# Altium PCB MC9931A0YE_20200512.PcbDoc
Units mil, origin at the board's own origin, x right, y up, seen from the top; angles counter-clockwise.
Board outline 1358.13 x 1061.66 mil, 2 copper layers (Top Layer, Bottom Layer); 25 components, 18 nets, 85 pads, 79 vias.
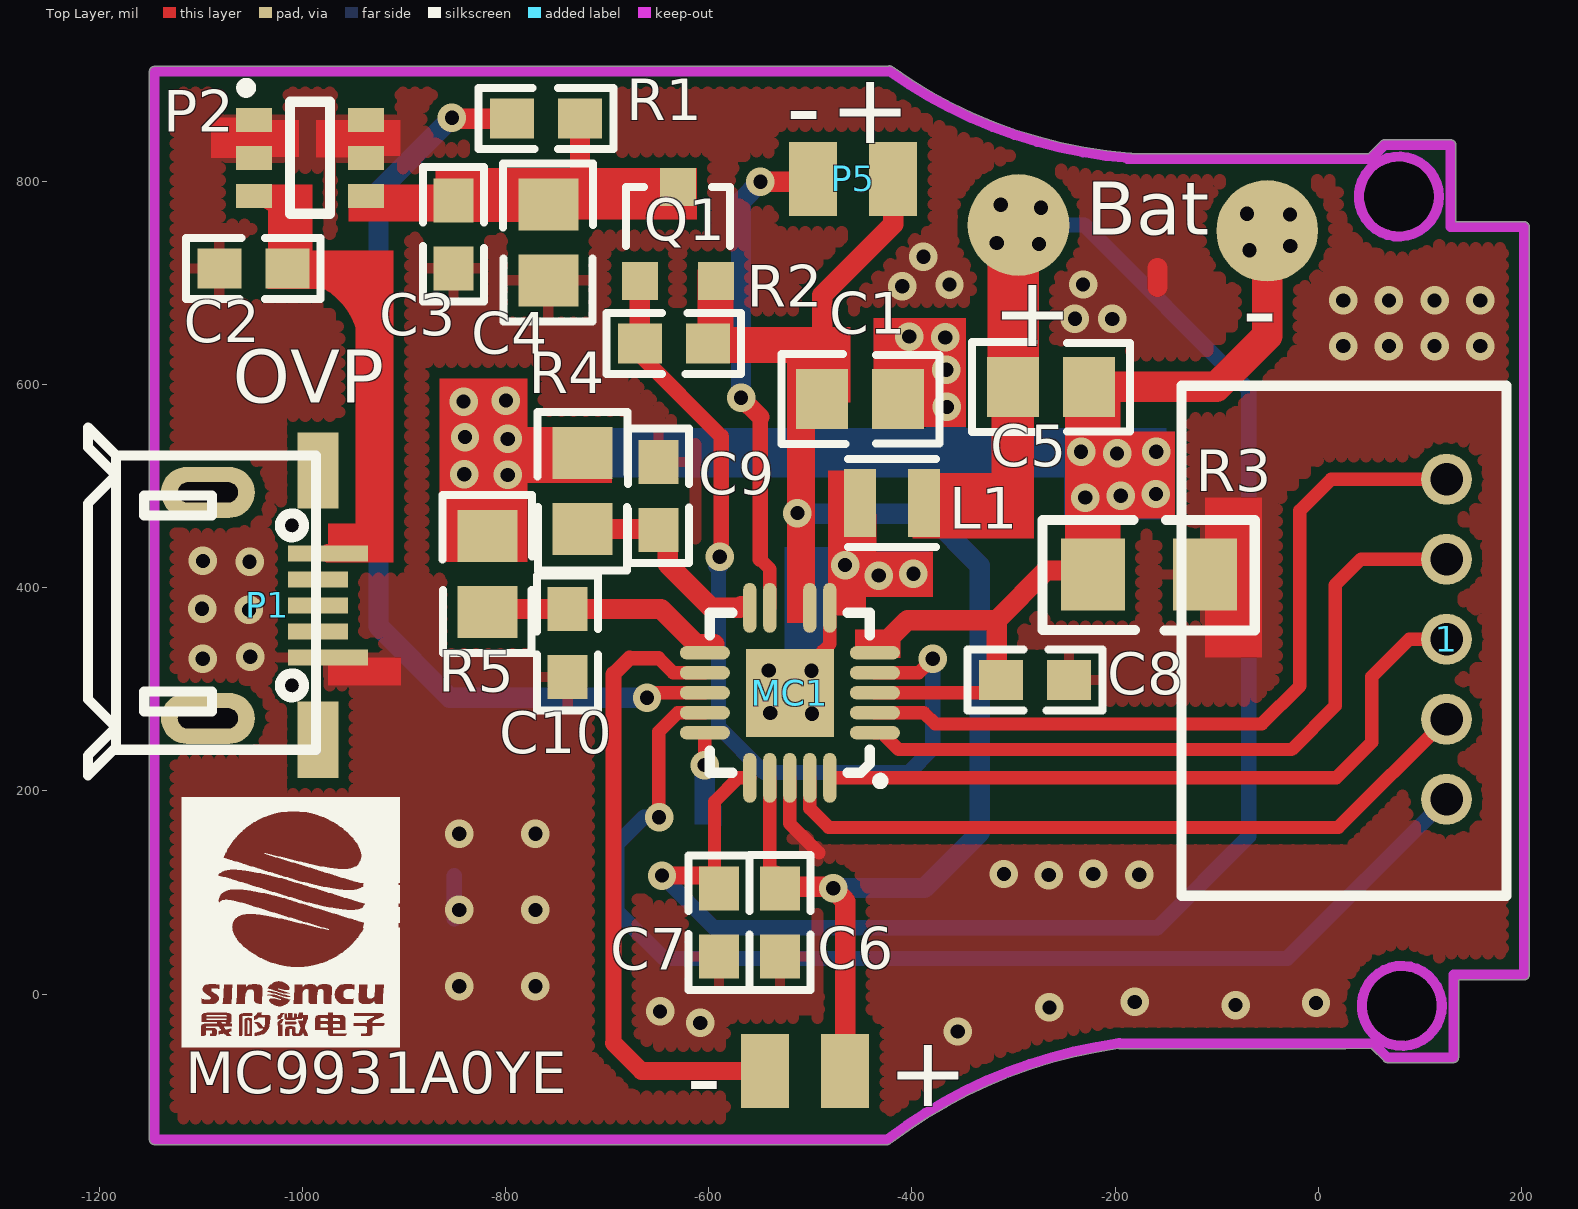
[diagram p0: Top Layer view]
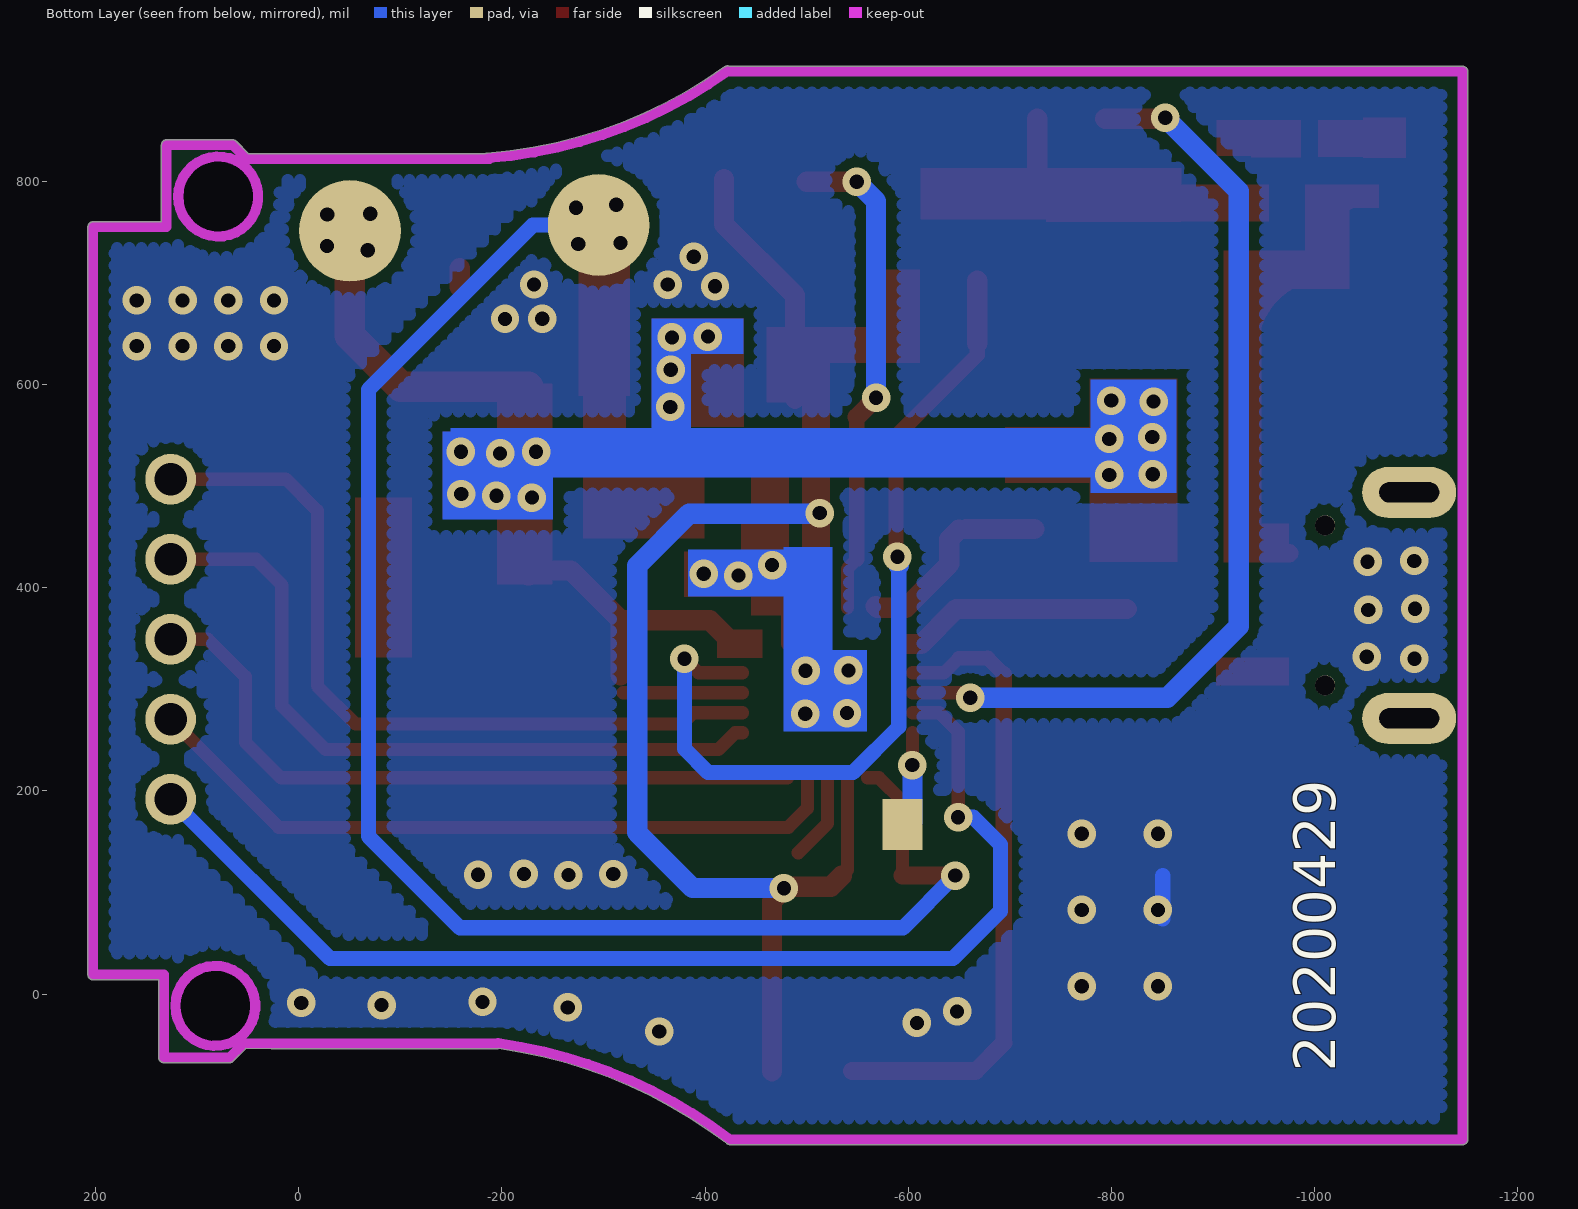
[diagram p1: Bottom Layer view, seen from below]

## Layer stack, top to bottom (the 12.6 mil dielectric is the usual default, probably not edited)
Top Layer: signal copper 1.4
Dielectric: dielectric 12.6, FR-4, Dk 4.8
Bottom Layer: signal copper 1.4

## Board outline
-1145.59,-148.2 -424.37,-148.2 ccw(c-424.33,-143.18) -421.28,-147.17 cw(c-131.52,-526.41) -196.65,-53.6 ccw(c-195.83,-48.65) -195.83,-53.67 27.1,-53.66 ccw(c27.1,-48.65) 27.15,-53.66 51.99,-53.55 64.47,-66.03 64.46,-66.01 ccw(c68.02,-62.48) 68.02,-67.5 132.95,-67.5 ccw(c132.95,-62.48) 137.96,-62.48 137.96,13.97 202.51,13.97 ccw(c202.51,18.98) 207.52,18.98 207.52,755.06 ccw(c202.51,755.06) 202.51,760.08 135.14,760.08 135.14,835.8 ccw(c130.12,835.8) 130.12,840.82 65.19,840.82 ccw(c65.19,835.8) 61.63,839.33 61.65,839.35 49.16,826.86 24.32,826.98 24.3,826.98 24.32,826.98 ccw(c24.27,821.96) 24.27,826.98 -183.11,826.88 ccw(c-185.92,822.72) -185.53,827.72 cw(c-149.89,1290.25) -419.21,912.54 ccw(c-422.13,908.45) -424.21,913.01 ccw(c-424.33,908) -424.33,913.01 -1145.59,913.01 ccw(c-1145.59,908) -1150.6,908 -1150.6,-143.18 ccw(c-1145.59,-143.18)
cut-out: 39.94,784.95 ccw(c79.31,784.95) 79.31,745.58 ccw(c79.31,784.95) 118.68,784.95 ccw(c79.31,784.95) 79.31,824.32 ccw(c79.31,784.95)
cut-out: 42.77,-11.63 cw(c82.14,-11.63) 82.14,27.74 cw(c82.14,-11.63) 121.51,-11.63 cw(c82.14,-11.63) 82.14,-51 cw(c82.14,-11.63)

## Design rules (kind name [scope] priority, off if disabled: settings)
Clearance [All] p1: gap=6
PolygonConnect [All] p1: connectstyle=Relief reliefconductorwidth=10 reliefentries=4 polygonreliefangle="90 Angle"
RoutingVias [All] p1: holewidth=28 width=50 viastyle="Through Hole" minholewidth=28 minwidth=50 maxholewidth=28 maxwidth=50
SilkToSilkClearance [All] p1 off: silktosilkclearance=10
SilkscreenOverComponentPads [All] p1 off: minsilkscreentomaskgap=10
SolderMaskExpansion [All] p1: expansion=4
Width [All] p1: maxlimit=50 minlimit=9 preferedwidth=15
26 further rules are at their usual default settings.

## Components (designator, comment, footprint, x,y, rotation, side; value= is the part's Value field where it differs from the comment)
1 "Header 5" 数码管_5脚 126.11,191.69 r90 top locked
+ "Header 2" 1焊盘 -295.11,756.86 r0 top (schematic designator P3)
+ "Header 2" 1*2焊盘 -465.72,-75.87 r180 top (schematic designator P6)
- "Header 2" 1焊盘 -50.38,751.16 r0 top (schematic designator P4)
C1 "Cap" 0805 -413.59,580.82 r180 top
C2 "Cap" 0603 -1081.79,714.13 r0 top
C3 "Cap" 0603 -851.14,714.34 r90 top
C4 "Cap" 0805 -762.98,702.47 r90 top
C5 "Cap" 0805 -225.83,592.63 r180 top
C6 "Cap" 0603 -530.03,103.79 r270 top
C7 "Cap" 0603 -590.01,36.76 r90 top
C8 "Cap" 0603 -245.39,309.12 r180 top
C9 "Cap" 0603 -649.43,456.85 r90 top
C10 "Cap" 0603 -738.88,379.04 r270 top
L1 "4.7uH" 电感SMD_201610 -419.42,483.17 r0 top
MC1 "MC9931A0ZQ" "QFN20_4*4 _Large" -520.25,296.5 r180 top locked
P1 "MicroUSB" MICRO-USB_standard -984.68,382.53 r270 top locked
P2 "LP5300B6F" SOT23-6 -992.33,823.06 r180 top
P5 "Header 2" 1*2焊盘 -418.51,802.25 r180 top
Q1 "3401" SOT-23_PMOS -667.79,701.92 r0 top
R1 "Res2" 0603 -793.64,861.6 r0 top
R2 "Res2" 0603 -600.86,640.47 r180 top
R3 "Res2" 1206 -111.69,412.96 r180 top
R4 "Res2" 0805 -729.06,457.63 r90 top
R5 "Res2" 0805 -822.83,376.04 r90 top

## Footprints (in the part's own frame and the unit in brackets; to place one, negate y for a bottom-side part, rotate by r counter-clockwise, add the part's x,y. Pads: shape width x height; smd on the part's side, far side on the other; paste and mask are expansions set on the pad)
1*2焊盘 [mm]
  rect 1.2x1.85 smd: 1(0,0) 2(2,0)
1焊盘 [mil] "Connector; Header; 2 Pos"
  round 100 all layers, no hole: 1(0,0)
0603 [mm]
  rect 1.1x1 smd: 1(0,0) 2(1.7,0)
  silkscreen extent -0.83,-0.76 2.53,0.76
0805 [mm]
  rect 1.3x1.5 smd: 1(0,-0.127) 2(1.9,-0.127)
  silkscreen extent -1.03,-1.24 2.92,1
1206 [mm]
  rect 1.6x1.8 smd: 1(0,0) 2(2.8,0)
  silkscreen extent -1.25,-1.36 4.06,1.4
MICRO-USB_standard [mm]
  rect 0.4x2 smd: 1(-1.3,0.25) 5(1.3,0.25)
  rect 0.4x1.5 smd: 2(-0.65,0) 3(0,0) 4(0.65,0)
  rect 1.905x1.016 smd: 6(3.357,0) 7(-3.374,0)
  oval 1.27x2.35 hole 0.5 slot 1.5 at 90 deg: 8(2.825,-2.75) 9(-2.825,-2.75)
  round 0.5 hole 0.5: 10(-2,-0.65) 11(2,-0.65)
  silkscreen extent -4.45,-5.75 4.25,-0.05
"QFN20_4*4 _Large" [mm]
  oval 1.25x0.33 smd: 1(-2.125,1) 2(-2.125,0.5) 3(-2.125,0) 4(-2.125,-0.5) 5(-2.125,-1) 11(2.125,-1) 12(2.125,-0.5) 13(2.125,0) 14(2.125,0.5) 15(2.125,1)
  oval 0.33x1.25 smd: 6(-1,-2.125) 7(-0.5,-2.125) 9(0.5,-2.125) 10(1,-2.125) 16(1,2.125) 17(0.5,2.125) 18(0,2.125) 19(-0.5,2.125) 20(-1,2.125)
  oval 0.33x1.25 on Top Overlay: 8(0,-2.125)
  rect 2.2x2.2 smd: 21(0,0)
  silkscreen extent -2.34,-2 2,2.28
SOT23-6 [mm]
  rect 0.9x0.6 smd: 1(1.4,-0.95) 2(1.4,0) 3(1.4,0.95) 4(-1.4,0.95) 5(-1.4,0) 6(-1.4,-0.95)
  silkscreen extent -0.5,-1.87 1.72,1.4
SOT-23_PMOS [mm]
  rect 0.9x0.95 smd: 1(0,0) 2(0.95,2.35) 3(1.9,0)
  silkscreen extent -0.35,0.87 2.25,2.35
数码管_5脚 [mil]
  round 50 hole 32: 1(0,0) 2(78.74,0) 3(157.48,0) 4(236.22,0) 5(314.96,0)
  silkscreen extent -95,-59 407,261
电感SMD_201610 [mm]
  rect 0.8x1.7 smd: 1(-0.8,0) 2(0.8,0)
  silkscreen extent -1.1,-1.1 1.1,1.1

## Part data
+ -: "Header, 2-Pin"
C4 C5: "Capacitor"
P2: library part "Header 3X2A", "Header, 3-Pin, Dual row"
Q1: library part PMOS-2

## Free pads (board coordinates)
  rect 39.37x50 smd far side: 0(-594.01,166.89)

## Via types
v1: diameter 28, hole 14, Top Layer to Bottom Layer, 79 vias

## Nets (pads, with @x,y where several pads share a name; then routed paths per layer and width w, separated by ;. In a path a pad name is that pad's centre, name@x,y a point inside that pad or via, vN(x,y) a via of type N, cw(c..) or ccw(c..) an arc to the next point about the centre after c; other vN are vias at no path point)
BAT+: +.1@-295.11,756.86 C5.2 C7.2 L1.2 MC1.16 | length 1538.4
  Top Layer w13: C7.2@-594.32,116.61 -594.32,189.49 -570.97,212.84 MC1.16
  Top Layer w18: v1(-646.06,116.61) C7.2@-594.32,116.61
  Bottom Layer w15: v1(-646.06,116.61) -594.61,65.17 -158.63,65.17 -68.62,155.17 -68.62,595.11 -230.37,756.86 +.1@-295.11,756.86
  other v1: -275.1,738.29 -316.59,739.25 -272.93,773.86 -312.56,776.83
BAT-: -.1 C1.1 C5.1 C8.2 MC1.3 MC1.5 R3.2 R4.2 R5.2 | length 1039.9
  Top Layer w13: MC1.3 C8.2@-319.35,296.5
  Top Layer w20: R5.2@-808.64,452.43 -808.64,511 -787.21,532.43 R4.2 ; MC1.5@-430.57,341.88 -404.45,368 -316.71,368 ; C8.2@-316.71,313.51 -316.71,368 ; R3.2@-225.83,416.86 -267.85,416.86 -316.71,368
  Top Layer w30: R3.2@-225.83,416.86 C5.1 -100.52,597.63 -50.38,647.77 -.1
  other v1: -229.44,488.6 -194.53,490.51 -159.89,492.14 -797.81,510.91 -840.58,511.63 -198.13,532.13 -233.52,533.7 -159.58,533.7 -797.81,546.34 -839.95,548.17 -365.64,577.87 -841.29,583.16 -799.62,584.12 -366.19,614.49 -367.29,646.28 -402.64,647.07 -67.9,732.13 -27.74,736.35 -27.98,767.23 -70.31,767.95
GND: C2.1 C3.1 C4.1 C6.2 C7.1 C8.1 C9.2 C10.2 MC1.18 P1.5 P2.1 P2.2 P2.5 P2.6 R3.1 | length 146.4
  Top Layer w13: MC1.18 -520.25,167.75 -491.58,139.08
  Top Layer w20: -158.41,696.08 -158.41,714.57
  Bottom Layer w15: v1@-850.41,74.09 -850.41,116.41
  other v1: -354.87,-36.88 -608.35,-28.41 -647.93,-17.1 -264.67,-13.15 -81.46,-10.93 -2.35,-8.72 -180.82,-7.77 -845.62,7.73 -770.62,7.73 -845.62,82.73 -770.62,82.73 -265.37,117.02 -176.39,117.31 -309.52,118.14 -221.6,118.17 -845.62,157.73 -770.62,157.73 -1098.1,330.03 -1051.24,331.96 -1052.59,378.04 -1098.68,379.2 -1052.02,425.48 -1097.91,426.25 24.38,637.73 69.38,637.73 114.38,637.73 159.38,637.73 -202.99,664.47 -239.64,664.7 24.38,682.73 69.38,682.73 114.38,682.73 159.38,682.73 -409.65,696.55 -363.05,698.27 -231.54,698.35 -388.74,725.66
LED_1: 1.1 MC1.14 | length 1156.6
  Top Layer w13: v1@-649.16,174.04 -649.16,258.14 -630.49,276.82 MC1.14
  Bottom Layer w15: v1(-648.92,174.04) -663.77,174.04 -690.66,147.15 -690.66,81.51 -644.03,34.88 -30.7,34.88 1.1
LED_2: 1.2 MC1.19 | length 708.6
  Top Layer w13: MC1.19 -500.56,182.72 -481.86,164.01 19.69,164.01 1.2
LED_3: 1.3 MC1.20 | length 701.3
  Top Layer w13: MC1.20 17.63,212.84 52.51,247.72 52.51,312.24 89.45,349.17 1.3
LED_4: 1.4 MC1.1 | length 716.9
  Top Layer w13: MC1.1 -429.64,257.13 -413.08,240.57 -26.44,240.57 16.67,283.68 16.67,402.65 41.93,427.91 1.4
LED_5: 1.5 MC1.2 | length 768.2
  Top Layer w13: MC1.2 -388.31,276.82 -377.3,265.81 -55.75,265.81 -18.4,303.16 -18.4,475.82 12.44,506.65 1.5
LOADCURRENT_1: C9.1 MC1.10 R4.1 | length 195.2
  Top Layer w20: R4.1 C9.1@-657.11,457.63 ; C9.1 -640.38,447.8 -640.38,423.18 -597.36,380.16 -569.27,380.16 -567.9,381.53
LOADCURRENT_2: C10.1 MC1.11 R5.1 | length 234.6
  Top Layer w20: R5.1@-814.83,379.04 C10.1 -647.08,379.04 -612.52,344.48 -594.5,344.48
LOADIN_1: MC1.9 P5.2 | length 487.9
  Top Layer w13: -549.24,427.72 -539.93,418.41 MC1.9
  Top Layer w15: -549.24,427.72 -549.24,567.9
  Top Layer w18: v1(-568.21,586.87) -549.24,567.9
  Top Layer w20: v1(-549.23,799.4) P5.2@-500.09,799.4
  Bottom Layer w20: v1(-568.21,586.87) -568.21,780.41 v1(-549.23,799.4)
LOADIN_2: +.2 MC1.12 | length 626.2
  Top Layer w13: -649.48,330.49 -635.17,316.19 MC1.12
  Top Layer w14: -678.09,330.49 -649.48,330.49
  Top Layer w15: -693.88,314.7 -678.09,330.49
  Top Layer w16: -693.88,-48.1 -693.88,314.7
  Top Layer w17: -693.88,-48.1 -666.12,-75.87
  Top Layer w18: -666.12,-75.87 +.2
NetC3_2: C3.2 C4.2 P2.4 Q1.2 R1.2 | length 389.1
  Top Layer w20: P2.4 ccw(c-932.83,785.65) -932.83,781.27 C3.2 -761.97,781.27 cw(c-761.97,777.28) C4.2 cw(c-740.82,777.28) -740.82,794.44 C4.2@-730.07,794.44 ; R1.2 -726.71,808.55 cw(c-757.98,808.55) C4.2@-730.07,794.44 ; Q1.2 C4.2@-730.07,794.44
NMS-D: L1.1 MC1.6 MC1.21 | length 100
  Top Layer w12: MC1.21 MC1.21@-488.12,328.63 ; MC1.21@-488.12,337.36 -480.88,344.6
  Top Layer w13: MC1.21@-488.12,328.63 MC1.21@-488.12,337.36 ; -480.88,344.6 MC1.6
  other v1: -498.5,275.8 -539.56,276.54 -498.82,318.23 -540.93,318.55 -432.69,411.87 -398.64,413.61 -465.8,422.18
USB: C2.2 P1.1 P2.3 | length 449.2
  Top Layer w18: P1.1 -954.29,433.72 ccw(c-954.29,454.31) -933.7,454.31
  Top Layer w20: P2.3 cw(c-1047.45,753.06) -1014.86,753.06 C2.2 cw(c-1014.86,632.97) -933.7,632.97 -933.7,454.31
USB_VOL: MC1.13 R1.1 | length 941
  Top Layer w13: v1(-660.78,291.7) -655.98,296.5 MC1.13
  Top Layer w20: v1@-851.85,861.6 R1.1
  Bottom Layer w20: v1(-852.8,862.56) -925.07,790.28 -925.07,361.97 -854.79,291.7 v1(-660.78,291.7)
USBIN_CTRL: MC1.4 Q1.1 R2.2 | length 862.6
  Top Layer w13: MC1.4 -393.42,316.19 v1(-379.57,330.03)
  Top Layer w15: R2.2 -667.79,628.96 -587.82,548.99 v1@-587.82,430.28
  Top Layer w20: R2.2 Q1.1
  Bottom Layer w15: v1@-590.53,422.14 -590.53,263.05 -545.58,218.11 -402.9,218.11 -379.57,241.43 v1(-379.57,330.03)
  Bottom Layer w20: v1@-590.53,422.14 v1@-590.53,430.28
  other v1: -589.16,430.28
VDD: +.1@-465.72,-75.87 C1.2 C6.1 MC1.7 MC1.17 P5.1 Q1.3 R2.1 | length 1211
  Top Layer w13: C6.1@-539.93,121.94 MC1.17
  Top Layer w20: C6.1@-534.33,116.34 -523.71,105.72 -479.89,105.72 -465.72,91.55 +.1@-465.72,-75.87 ; C1.2 -488.4,687.71 -418.51,757.6 P5.1
  Bottom Layer w20: v1@-510.98,472.59 -384.07,472.59 -333.18,421.71 -333.18,158.96 -387.82,104.31 v1@-477.32,104.31
  other v1: -477.54,104.08 -512.7,473.41
pads on no net: MC1.8 MC1.15 P1.2 P1.3 P1.4 P1.6 P1.7 P1.8 P1.9 P1.10 P1.11
copper on no net: | length 48.3
  Top Layer w13: v1(-603.91,225.3) -603.91,257.13
  Bottom Layer w13: -594.01,166.89 -594.01,183.34

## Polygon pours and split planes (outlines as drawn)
GND on Top Layer "MultiLayer-No Net" (hatched 90Degree grid 12 track 12, remove dead copper, pour order 4): -1145.59,-143.18 -1145.59,966.26 332.58,966.26 288.12,966.26 288.12,-224.15 288.12,-143.18 -1145.59,-143.18
GND on Bottom Layer "MultiLayer-No Net" (hatched 90Degree grid 12 track 12, remove dead copper, pour order 6): -1145.59,-143.18 328.72,-143.18 328.72,972.14 328.72,908 -1145.59,908 -1145.59,-143.18

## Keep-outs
Keep-Out Layer:
  circle w10: c82.14,-11.63 r39.37
  circle w10: c79.31,784.95 r39.37
  lines w10: -424.33,908 -1145.59,908 -1145.59,-143.18 -424.33,-143.18 cw(c-131.52,-526.41) -196.05,-48.46 ; -422.13,908.45 ccw(c-149.89,1290.25) -185.92,822.72 ; -195.83,-48.65 27.1,-48.65 54.06,-48.52 68.02,-62.48 132.95,-62.48 132.95,18.98 202.51,18.98 202.51,755.06 130.12,755.06 130.12,835.8 65.19,835.8 51.23,821.84 24.27,821.96 -187.65,821.86

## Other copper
Top Layer:
  rectangle net NMS-D: -452,426.17 -435.04,472.26
  rectangle net NMS-D: -476.49,390.67 -379.19,435.36
  rectangle net GND: -974.84,303.57 -902.82,331.35
  rectangle net GND: -111.62,331.39 -55.56,488.79
  rectangle net GND: -986.39,823.24 -937.22,860.46
  rectangle net GND: -937.22,825 -903.5,860.46
  rectangle net GND: -1047.45,823.81 -1003.37,860.46
  rectangle net GND: -1089.71,823.06 -1047.45,862.67
  rectangle net BAT-: -244.88,468.28 -141.24,553.88
  rectangle net BAT-: -249.48,403.19 -195,600.92
  rectangle net BAT-: -438,557.89 -346.96,665.41
  rectangle net BAT-: -865.12,425.03 -778.38,605.96
  rectangle net BAT-: -851.75,425.1 -784.35,557.9
  rectangle net BAT-: -851.75,503.02 -695.06,557.9
  rectangle net NetC3_2: -750.78,762.54 -611.82,812.93
  rectangle net NetC3_2: -869,759.67 -735.5,813.02
  rectangle net NetC3_2: -954.76,760.44 -833.39,796.85
  rectangle net USB: -1034.02,705.07 -990.15,796.98
  rectangle net USB: -1063.1,773.46 -990.15,796.98
  rectangle net USB: -1034.39,693.86 -910.15,732.04
  rectangle net USB: -947.74,424.72 -910.15,732.04
  rectangle net USB: -974.84,424.72 -910.15,463.05
  rectangle net BAT-: -456.18,330.61 -411.46,359
  rectangle net BAT+: -325.86,588.61 -275.1,764.97
  rectangle net BAT+: -399.3,448.19 -279.95,512.94
  rectangle net BAT+: -321.97,470.97 -279.95,620.64
  rectangle net VDD: -611.26,639.27 -575.44,712.97
  rectangle net VDD: -513.91,582 -460.49,656.66
  rectangle net VDD: -522.91,365.41 -495.41,656.66
  rectangle net VDD: -611.49,620.89 -460.49,656.66
  rectangle net NMS-D: -482.5,372.66 -445.2,515.13
Bottom Layer:
  rectangle net NMS-D: -525.55,391.03 -382.98,437.29
  rectangle net NMS-D: -525.55,332.75 -477,439.81
  rectangle net NMS-D: -559.14,258.2 -477,338.51
  rectangle: -614.05,166.89 -594.01,227.36
  rectangle net BAT-: -250.44,466.89 -141.4,553.42
  rectangle net BAT-: -437.78,630.06 -347.06,665.1
  rectangle net BAT-: -386.16,525.89 -347.06,665.1
  rectangle net BAT-: -839.95,508.53 -149.29,557.32
  rectangle net BAT-: -863.95,493.29 -779.25,604.71

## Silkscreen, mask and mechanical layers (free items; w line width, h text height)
Top Overlay:
  drawing of 2171 lines, arcs and shapes, not listed
  text "-" at -523.55,838.45 h70
  text "+" at -400.74,837.28 h70
  text "Bat" at -228.42,730.06 h90
  text "OVP" at -1068.56,564.51 h90
  text "MC9931A0YE" at -1115.17,-111.39 h70
  text "-" at -587.42,-116.29 h70
Bottom Overlay:
  text "20200429" at -1034.04,-76.66 h70 r270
